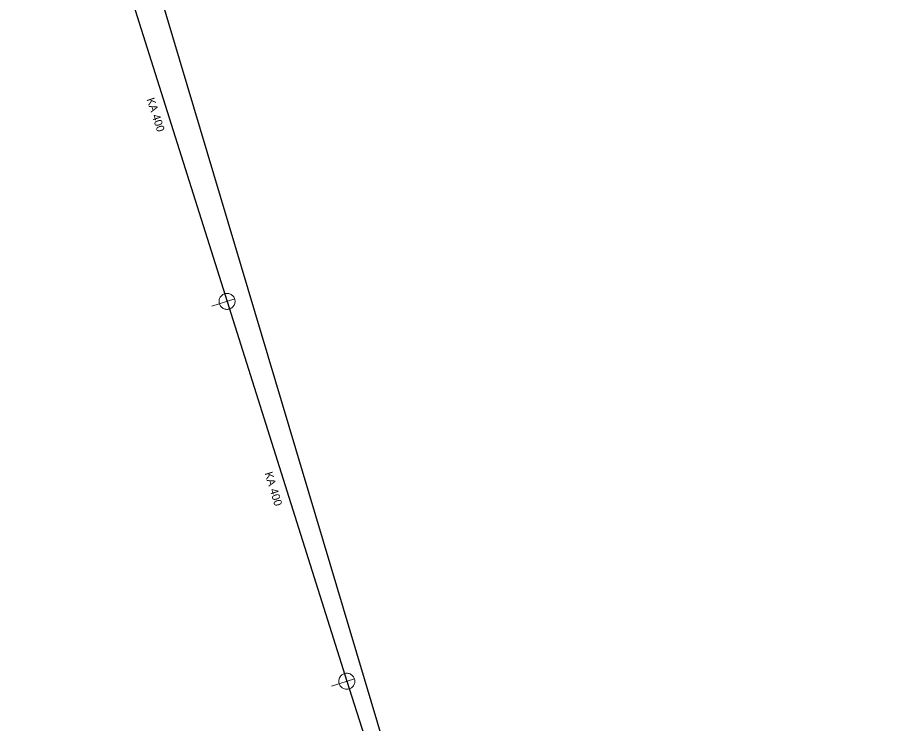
# Model space of a CAD drawing. Extents: x -807203 to -805207, y -993656 to -992505.
# Drawn here: x -807026.3 to -806918.3, y -993440.7 to -993352.4 of the extents above; entities that cross this region are included whole.
import ezdxf

# ---------------------------------------------------------------- set-up
doc = ezdxf.new("R2010")
doc.units = 0
doc.header["$LTSCALE"] = 0.4
for name, color, linetype, lineweight in [('1', 7, 'Continuous', 13), ('14', 7, 'Continuous', 25), ('17', 7, 'Continuous', 25), ('22', 7, 'Continuous', 13)]:
    doc.layers.add(name, color=color, linetype=linetype, lineweight=lineweight)

msp = doc.modelspace()

# ---------------------------------------------------------------- linework, layer by layer
at = {"layer": '14'}
for p, q in [((-807014.609, -993341.899), (-807000.09, -993387.89)), ((-807000.09, -993387.89), (-806985.14, -993435.35)), ((-806985.14, -993435.35), (-806970.039, -993482.12))]:
    msp.add_line(p, q, dxfattribs=at)
at = {"layer": '17'}
msp.add_lwpolyline([(-807026.284, -993334.262), (-807008.554, -993349.182), (-806918.346, -993651.677), (-806922.495, -993656.048)], dxfattribs=at)
at = {"layer": '22'}
for p, q in [((-807001.997, -993388.492), (-806999.136, -993387.589)), ((-806987.048, -993435.951), (-806984.186, -993435.049))]:
    msp.add_line(p, q, dxfattribs=at)
for points in [[(-806999.789, -993388.843), (-806999.687, -993388.805), (-806999.589, -993388.755), (-806999.497, -993388.695), (-806999.413, -993388.626), (-806999.336, -993388.547), (-806999.269, -993388.461), (-806999.211, -993388.367), (-806999.165, -993388.269), (-806999.128, -993388.165), (-806999.104, -993388.059), (-806999.092, -993387.95), (-806999.092, -993387.84), (-806999.103, -993387.731), (-806999.126, -993387.624), (-806999.161, -993387.52), (-806999.207, -993387.421), (-806999.263, -993387.327), (-806999.329, -993387.24), (-806999.406, -993387.161), (-806999.489, -993387.091), (-806999.58, -993387.029), (-806999.677, -993386.979), (-806999.78, -993386.939), (-806999.885, -993386.911), (-806999.993, -993386.894), (-807000.103, -993386.89), (-807000.212, -993386.897), (-807000.32, -993386.917), (-807000.425, -993386.948), (-807000.526, -993386.99), (-807000.622, -993387.042), (-807000.711, -993387.106), (-807000.793, -993387.178), (-807000.867, -993387.259), (-807000.931, -993387.349), (-807000.985, -993387.443), (-807001.029, -993387.544), (-807001.061, -993387.649), (-807001.081, -993387.756), (-807001.09, -993387.865), (-807001.087, -993387.975), (-807001.071, -993388.083), (-807001.044, -993388.19), (-807001.005, -993388.292), (-807000.956, -993388.389), (-807000.896, -993388.481), (-807000.827, -993388.566), (-807000.748, -993388.643), (-807000.662, -993388.71), (-807000.569, -993388.768), (-807000.47, -993388.815), (-807000.367, -993388.85), (-807000.26, -993388.876), (-807000.151, -993388.887), (-807000.042, -993388.889), (-806999.932, -993388.877), (-806999.825, -993388.854)], [(-806984.84, -993436.303), (-806984.737, -993436.265), (-806984.64, -993436.215), (-806984.548, -993436.155), (-806984.463, -993436.086), (-806984.386, -993436.008), (-806984.319, -993435.921), (-806984.262, -993435.828), (-806984.215, -993435.729), (-806984.179, -993435.626), (-806984.154, -993435.519), (-806984.142, -993435.41), (-806984.142, -993435.3), (-806984.153, -993435.192), (-806984.176, -993435.085), (-806984.211, -993434.98), (-806984.257, -993434.882), (-806984.313, -993434.787), (-806984.379, -993434.7), (-806984.455, -993434.621), (-806984.538, -993434.551), (-806984.63, -993434.49), (-806984.726, -993434.439), (-806984.829, -993434.399), (-806984.935, -993434.371), (-806985.043, -993434.354), (-806985.152, -993434.35), (-806985.262, -993434.357), (-806985.369, -993434.376), (-806985.474, -993434.408), (-806985.575, -993434.45), (-806985.671, -993434.502), (-806985.76, -993434.566), (-806985.842, -993434.638), (-806985.916, -993434.719), (-806985.981, -993434.808), (-806986.035, -993434.903), (-806986.078, -993435.004), (-806986.11, -993435.108), (-806986.131, -993435.215), (-806986.14, -993435.325), (-806986.137, -993435.434), (-806986.121, -993435.542), (-806986.094, -993435.649), (-806986.056, -993435.751), (-806986.006, -993435.849), (-806985.947, -993435.94), (-806985.877, -993436.025), (-806985.798, -993436.102), (-806985.712, -993436.169), (-806985.619, -993436.227), (-806985.521, -993436.275), (-806985.417, -993436.31), (-806985.311, -993436.335), (-806985.202, -993436.347), (-806985.093, -993436.349), (-806984.983, -993436.337), (-806984.876, -993436.314)]]:
    msp.add_lwpolyline(points, close=True, dxfattribs=at)

# ---------------------------------------------------------------- texts
at = {"layer": '1'}
for rotation, p in [(288, (-807010.146, -993362.631)), (287, (-806995.409, -993409.354))]:
    msp.add_text('KA 400', height=1, rotation=rotation, dxfattribs=at).set_placement(p)

doc.saveas('drawing.dxf')
